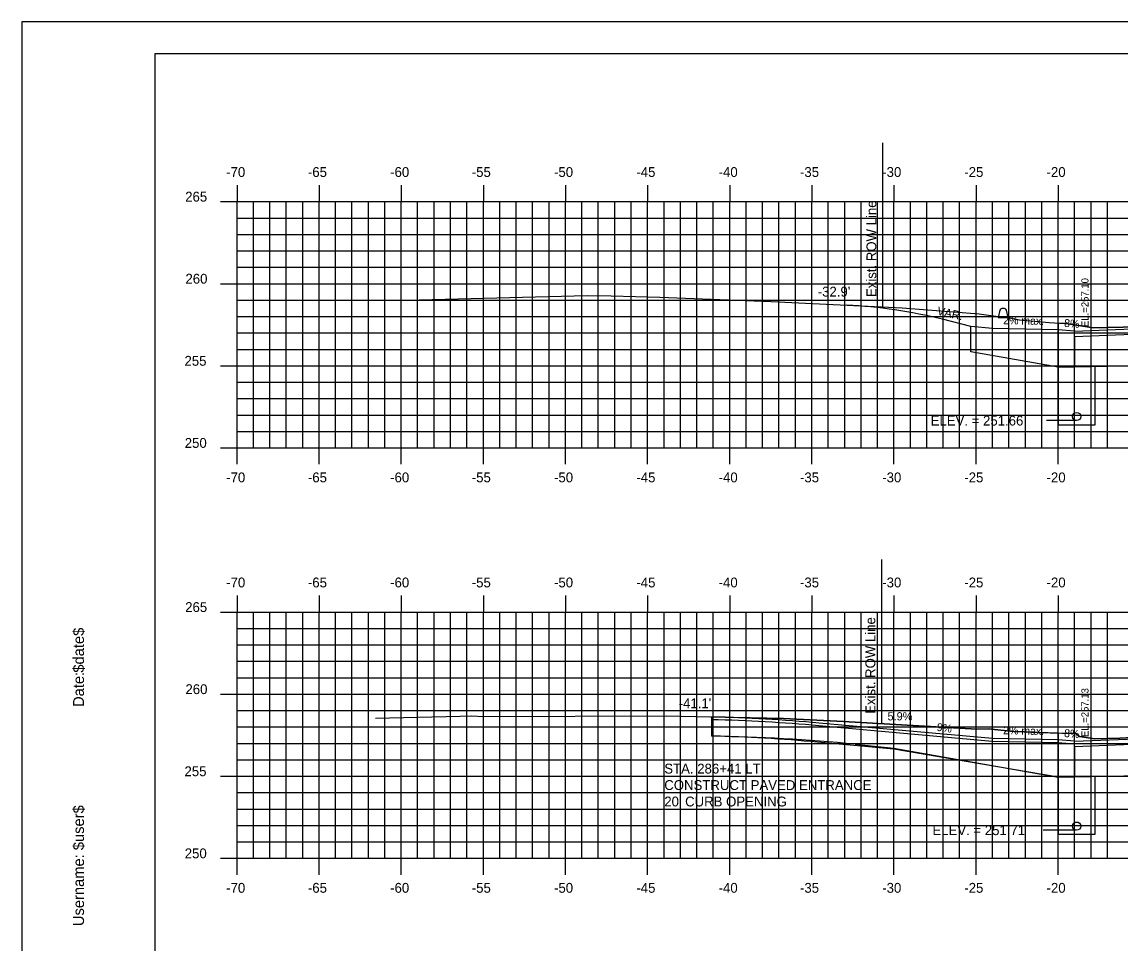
# Model space of a CAD drawing. Extents: x 856903 to 857073, y 366268 to 366378.
# Drawn here: x 856902.7 to 856969.5, y 366322.1 to 366378.2 of the extents above; entities that cross this region are included whole.
import ezdxf

# ---------------------------------------------------------------- set-up
doc = ezdxf.new("R2010")
doc.units = 0
for name, color, linetype in [('ANNOTATION', 7, 'Continuous'), ('BORDER', 7, 'Continuous'), ('D_Roadway_Drive_Gravel_LT', 7, 'Continuous'), ('D_Roadway_Drive_SubGrade', 7, 'Continuous'), ('D_Roadway_Edge_Shoulder', 7, 'Continuous'), ('D_Roadway_SubGrade', 7, 'Continuous'), ('D_Text_Standard', 7, 'Continuous'), ('E_ROW_Line', 7, 'Continuous'), ('H_V ANNOTATION', 7, 'Continuous'), ('JUNK COM EXC', 7, 'Continuous'), ('junk strct exc', 7, 'Continuous'), ('MAJOR', 7, 'Continuous'), ('MINOR', 7, 'Continuous'), ('PDRAIN', 7, 'Continuous'), ('PLOT BOUNDARY', 7, 'Continuous'), ('S_Curb_Type_3', 7, 'Continuous'), ('S_Roadway_Centerline', 7, 'Continuous'), ('TEXT', 7, 'Continuous')]:
    doc.layers.add(name, color=color, linetype=linetype)

msp = doc.modelspace()

# ---------------------------------------------------------------- linework, layer by layer
at = {"layer": 'BORDER'}
for p, q in [((857070.784, 366376.236), (856910.784, 366376.236)), ((856910.784, 366376.236), (856910.784, 366271.236))]:
    msp.add_line(p, q, dxfattribs=at)
at = {"layer": 'D_Roadway_Drive_Gravel_LT'}
for p, q in [((856960.471, 366359.632), (856958.739, 366360.065)), ((856960.471, 366358.094), (856960.471, 366359.632)), ((856961.784, 366359.501), (856960.471, 366359.632)), ((856965.784, 366359.421), (856961.784, 366359.501)), ((856966.784, 366359.341), (856965.784, 366359.421)), ((856966.784, 366359.007), (856966.784, 366359.341)), ((856961.784, 366334.523), (856951.234, 366335.473)), ((856961.769, 366334.357), (856951.219, 366335.307)), ((856955.784, 366333.892), (856951.129, 366334.311)), ((856965.781, 366334.277), (856961.781, 366334.357)), ((856965.784, 366334.443), (856961.784, 366334.523)), ((856961.784, 366334.523), (856961.784, 366334.523)), ((856966.784, 366334.196), (856965.771, 366334.277)), ((856966.784, 366334.363), (856965.784, 366334.443)), ((856966.784, 366334.03), (856966.784, 366334.363))]:
    msp.add_line(p, q, dxfattribs=at)
for centre, radius, start, end in [((856951.464, 366330.961), 30, 75.96376, 87.2318), ((856942.27, 366235.875), 100, 84.85724, 88.61888), ((856942.27, 366235.875), 99.833, 84.85724, 88.61657), ((856942.27, 366235.875), 98.833, 84.85724, 88.60257)]:
    msp.add_arc(centre, radius, start, end, dxfattribs=at)
at = {"layer": 'D_Roadway_Drive_SubGrade'}
for p, q in [((856965.784, 366357.147), (856960.471, 366358.094)), ((856966.784, 366357.167), (856965.784, 366357.147)), ((856944.68, 366335.846), (856944.68, 366334.679)), ((856965.784, 366332.17), (856955.784, 366333.892)), ((856966.784, 366332.19), (856965.784, 366332.17))]:
    msp.add_line(p, q, dxfattribs=at)
at = {"layer": 'D_Roadway_Edge_Shoulder'}
for points in [[(856966.784, 366359.341), (856974.784, 366359.661), (856985.784, 366359.881), (856996.784, 366359.661), (857004.785, 366359.341)], [(856966.784, 366334.363), (856974.784, 366334.683), (856985.784, 366334.903), (856996.784, 366334.683), (857004.785, 366334.363)]]:
    msp.add_lwpolyline(points, dxfattribs=at)
at = {"layer": 'D_Roadway_SubGrade'}
for points in [[(856974.784, 366359.327), (856966.784, 366359.007), (856966.784, 366357.167), (856974.784, 366357.327)], [(856974.784, 366334.35), (856966.784, 366334.03), (856966.784, 366332.19), (856974.784, 366332.35)]]:
    msp.add_lwpolyline(points, close=True, dxfattribs=at)
at = {"layer": 'D_Text_Standard'}
for points in [[(856966.909, 366353.896), (856965.746, 366353.896), (856965.066, 366353.896)], [(856966.909, 366328.946), (856965.544, 366328.946), (856964.864, 366328.946)]]:
    msp.add_lwpolyline(points, dxfattribs=at)
at = {"layer": 'E_ROW_Line'}
for p, q in [((856955.11, 366360.82), (856955.11, 366370.82)), ((856955.047, 366335.437), (856955.047, 366345.437))]:
    msp.add_line(p, q, dxfattribs=at)
at = {"layer": 'JUNK COM EXC'}
for points in [[(856970.642, 366359.617), (856967.936, 366359.549), (856966.278, 366359.805), (856966.269, 366359.812), (856966.267, 366359.811), (856966.192, 366359.813), (856965.784, 366359.836), (856965.784, 366357.147), (856974.784, 366357.327)], [(856965.784, 366334.855), (856964.556, 366334.889), (856963.708, 366334.937), (856963.082, 366334.961), (856961.517, 366335.116), (856960.827, 366335.095), (856952.722, 366335.574), (856949.051, 366335.741), (856946.005, 366335.814), (856944.68, 366335.846), (856944.68, 366334.679)], [(856953.429, 366334.186), (856955.784, 366333.951), (856965.784, 366332.17), (856965.784, 366334.855)], [(857005.784, 366334.674), (857004.443, 366334.819), (857002.913, 366334.984), (857002.611, 366334.676), (857002.347, 366334.388), (856998.4, 366334.53), (856996.854, 366334.558), (856988.735, 366334.939), (856985.845, 366335.02), (856977.64, 366334.888), (856975.733, 366334.868), (856969.543, 366334.552), (856968.014, 366334.513), (856967.076, 366334.658), (856966.809, 366334.862), (856966.744, 366334.828), (856965.784, 366334.855), (856965.784, 366332.17), (856974.784, 366332.35), (856985.784, 366332.57), (856996.784, 366332.35), (857005.784, 366332.17), (857005.784, 366334.674)]]:
    msp.add_lwpolyline(points, dxfattribs=at)
msp.add_arc((856942.508, 366218.264), 116.435, 84.61802, 88.93118, dxfattribs=at)
at = {"layer": 'junk strct exc'}
for points in [[(856965.784, 366357.147), (856965.784, 366353.646), (856968.034, 366353.646), (856968.034, 366357.192)], [(856965.784, 366332.197), (856965.784, 366328.696), (856968.034, 366328.696), (856968.034, 366332.215)]]:
    msp.add_lwpolyline(points, close=True, dxfattribs=at)
at = {"layer": 'MAJOR'}
for p, q in [((856915.784, 366368.238), (856915.784, 366367.236)), ((856920.784, 366368.238), (856920.784, 366367.236)), ((856925.784, 366368.238), (856925.784, 366367.236)), ((856930.784, 366368.238), (856930.784, 366367.236)), ((856935.784, 366368.238), (856935.784, 366367.236)), ((856940.784, 366368.238), (856940.784, 366367.236)), ((856945.784, 366368.238), (856945.784, 366367.236)), ((856950.784, 366368.238), (856950.784, 366367.236)), ((856955.784, 366368.238), (856955.784, 366367.236)), ((856960.784, 366368.238), (856960.784, 366367.236)), ((856965.784, 366368.238), (856965.784, 366367.236)), ((856914.782, 366367.236), (856915.784, 366367.236)), ((856915.784, 366367.236), (857055.784, 366367.236)), ((856915.784, 366352.236), (856915.784, 366367.236)), ((856915.784, 366352.236), (856915.784, 366367.236)), ((856915.784, 366367.236), (857055.784, 366367.236)), ((856920.784, 366352.236), (856920.784, 366367.236)), ((856925.784, 366352.236), (856925.784, 366367.236)), ((856930.784, 366352.236), (856930.784, 366367.236)), ((856935.784, 366352.236), (856935.784, 366367.236)), ((856940.784, 366352.236), (856940.784, 366367.236)), ((856945.784, 366352.236), (856945.784, 366367.236)), ((856950.784, 366352.236), (856950.784, 366367.236)), ((856955.784, 366352.236), (856955.784, 366367.236)), ((856960.784, 366352.236), (856960.784, 366367.236)), ((856965.784, 366352.236), (856965.784, 366367.236)), ((856914.782, 366362.236), (856915.784, 366362.236)), ((856915.784, 366362.236), (857055.784, 366362.236)), ((856914.782, 366357.236), (856915.784, 366357.236)), ((856915.784, 366357.236), (857055.784, 366357.236)), ((856914.782, 366352.236), (856915.784, 366352.236)), ((856915.784, 366352.236), (857055.784, 366352.236)), ((856915.784, 366352.236), (857055.784, 366352.236)), ((856915.784, 366351.234), (856915.784, 366352.236)), ((856920.784, 366351.234), (856920.784, 366352.236)), ((856925.784, 366351.234), (856925.784, 366352.236)), ((856930.784, 366351.234), (856930.784, 366352.236)), ((856935.784, 366351.234), (856935.784, 366352.236)), ((856940.784, 366351.234), (856940.784, 366352.236)), ((856945.784, 366351.234), (856945.784, 366352.236)), ((856950.784, 366351.234), (856950.784, 366352.236)), ((856955.784, 366351.234), (856955.784, 366352.236)), ((856960.784, 366351.234), (856960.784, 366352.236)), ((856965.784, 366351.234), (856965.784, 366352.236)), ((856915.784, 366343.238), (856915.784, 366342.236)), ((856920.784, 366343.238), (856920.784, 366342.236)), ((856925.784, 366343.238), (856925.784, 366342.236)), ((856930.784, 366343.238), (856930.784, 366342.236)), ((856935.784, 366343.238), (856935.784, 366342.236)), ((856940.784, 366343.238), (856940.784, 366342.236)), ((856945.784, 366343.238), (856945.784, 366342.236)), ((856950.784, 366343.238), (856950.784, 366342.236)), ((856955.784, 366343.238), (856955.784, 366342.236)), ((856960.784, 366343.238), (856960.784, 366342.236)), ((856965.784, 366343.238), (856965.784, 366342.236)), ((856914.782, 366342.236), (856915.784, 366342.236)), ((856915.784, 366342.236), (857055.784, 366342.236)), ((856915.784, 366327.236), (856915.784, 366342.236)), ((856915.784, 366327.236), (856915.784, 366342.236)), ((856915.784, 366342.236), (857055.784, 366342.236)), ((856920.784, 366327.236), (856920.784, 366342.236)), ((856925.784, 366327.236), (856925.784, 366342.236)), ((856930.784, 366327.236), (856930.784, 366342.236)), ((856935.784, 366327.236), (856935.784, 366342.236)), ((856940.784, 366327.236), (856940.784, 366342.236)), ((856945.784, 366327.236), (856945.784, 366342.236)), ((856950.784, 366327.236), (856950.784, 366342.236)), ((856955.784, 366327.236), (856955.784, 366342.236)), ((856960.784, 366327.236), (856960.784, 366342.236)), ((856965.784, 366327.236), (856965.784, 366342.236)), ((856914.782, 366337.236), (856915.784, 366337.236)), ((856915.784, 366337.236), (857055.784, 366337.236)), ((856914.782, 366332.236), (856915.784, 366332.236)), ((856915.784, 366332.236), (857055.784, 366332.236)), ((856914.782, 366327.236), (856915.784, 366327.236)), ((856915.784, 366327.236), (857055.784, 366327.236)), ((856915.784, 366327.236), (857055.784, 366327.236)), ((856915.784, 366326.234), (856915.784, 366327.236)), ((856920.784, 366326.234), (856920.784, 366327.236)), ((856925.784, 366326.234), (856925.784, 366327.236)), ((856930.784, 366326.234), (856930.784, 366327.236)), ((856935.784, 366326.234), (856935.784, 366327.236)), ((856940.784, 366326.234), (856940.784, 366327.236)), ((856945.784, 366326.234), (856945.784, 366327.236)), ((856950.784, 366326.234), (856950.784, 366327.236)), ((856955.784, 366326.234), (856955.784, 366327.236)), ((856960.784, 366326.234), (856960.784, 366327.236)), ((856965.784, 366326.234), (856965.784, 366327.236))]:
    msp.add_line(p, q, dxfattribs=at)
at = {"layer": 'MINOR'}
for p, q in [((856916.784, 366352.236), (856916.784, 366367.236)), ((856917.784, 366352.236), (856917.784, 366367.236)), ((856918.784, 366352.236), (856918.784, 366367.236)), ((856919.784, 366352.236), (856919.784, 366367.236)), ((856921.784, 366352.236), (856921.784, 366367.236)), ((856922.784, 366352.236), (856922.784, 366367.236)), ((856923.784, 366352.236), (856923.784, 366367.236)), ((856924.784, 366352.236), (856924.784, 366367.236)), ((856926.784, 366352.236), (856926.784, 366367.236)), ((856927.784, 366352.236), (856927.784, 366367.236)), ((856928.784, 366352.236), (856928.784, 366367.236)), ((856929.784, 366352.236), (856929.784, 366367.236)), ((856931.784, 366352.236), (856931.784, 366367.236)), ((856932.784, 366352.236), (856932.784, 366367.236)), ((856933.784, 366352.236), (856933.784, 366367.236)), ((856934.784, 366352.236), (856934.784, 366367.236)), ((856936.784, 366352.236), (856936.784, 366367.236)), ((856937.784, 366352.236), (856937.784, 366367.236)), ((856938.784, 366352.236), (856938.784, 366367.236)), ((856939.784, 366352.236), (856939.784, 366367.236)), ((856941.784, 366352.236), (856941.784, 366367.236)), ((856942.784, 366352.236), (856942.784, 366367.236)), ((856943.784, 366352.236), (856943.784, 366367.236)), ((856944.784, 366352.236), (856944.784, 366367.236)), ((856946.784, 366352.236), (856946.784, 366367.236)), ((856947.784, 366352.236), (856947.784, 366367.236)), ((856948.784, 366352.236), (856948.784, 366367.236)), ((856949.784, 366352.236), (856949.784, 366367.236)), ((856951.784, 366352.236), (856951.784, 366367.236)), ((856952.784, 366352.236), (856952.784, 366367.236)), ((856953.784, 366352.236), (856953.784, 366367.236)), ((856954.784, 366352.236), (856954.784, 366367.236)), ((856956.784, 366352.236), (856956.784, 366367.236)), ((856957.784, 366352.236), (856957.784, 366367.236)), ((856958.784, 366352.236), (856958.784, 366367.236)), ((856959.784, 366352.236), (856959.784, 366367.236)), ((856961.784, 366352.236), (856961.784, 366367.236)), ((856962.784, 366352.236), (856962.784, 366367.236)), ((856963.784, 366352.236), (856963.784, 366367.236)), ((856964.784, 366352.236), (856964.784, 366367.236)), ((856966.784, 366352.236), (856966.784, 366367.236)), ((856967.784, 366352.236), (856967.784, 366367.236)), ((856968.784, 366352.236), (856968.784, 366367.236)), ((856915.784, 366366.236), (857055.784, 366366.236)), ((856915.784, 366366.236), (856916.786, 366366.236)), ((856915.784, 366365.236), (857055.784, 366365.236)), ((856915.784, 366365.236), (856916.786, 366365.236)), ((856915.784, 366364.236), (857055.784, 366364.236)), ((856915.784, 366364.236), (856916.786, 366364.236)), ((856915.784, 366363.236), (857055.784, 366363.236)), ((856915.784, 366363.236), (856916.786, 366363.236)), ((856915.784, 366361.236), (857055.784, 366361.236)), ((856915.784, 366361.236), (856916.786, 366361.236)), ((856915.784, 366360.236), (857055.784, 366360.236)), ((856915.784, 366360.236), (856916.786, 366360.236)), ((856915.784, 366359.236), (857055.784, 366359.236)), ((856915.784, 366359.236), (856916.786, 366359.236)), ((856915.784, 366358.236), (857055.784, 366358.236)), ((856915.784, 366358.236), (856916.786, 366358.236)), ((856915.784, 366356.236), (857055.784, 366356.236)), ((856915.784, 366356.236), (856916.786, 366356.236)), ((856915.784, 366355.236), (857055.784, 366355.236)), ((856915.784, 366355.236), (856916.786, 366355.236)), ((856915.784, 366354.236), (857055.784, 366354.236)), ((856915.784, 366354.236), (856916.786, 366354.236)), ((856915.784, 366353.236), (857055.784, 366353.236)), ((856915.784, 366353.236), (856916.786, 366353.236)), ((856916.784, 366327.236), (856916.784, 366342.236)), ((856917.784, 366327.236), (856917.784, 366342.236)), ((856918.784, 366327.236), (856918.784, 366342.236)), ((856919.784, 366327.236), (856919.784, 366342.236)), ((856921.784, 366327.236), (856921.784, 366342.236)), ((856922.784, 366327.236), (856922.784, 366342.236)), ((856923.784, 366327.236), (856923.784, 366342.236)), ((856924.784, 366327.236), (856924.784, 366342.236)), ((856926.784, 366327.236), (856926.784, 366342.236)), ((856927.784, 366327.236), (856927.784, 366342.236)), ((856928.784, 366327.236), (856928.784, 366342.236)), ((856929.784, 366327.236), (856929.784, 366342.236)), ((856931.784, 366327.236), (856931.784, 366342.236)), ((856932.784, 366327.236), (856932.784, 366342.236)), ((856933.784, 366327.236), (856933.784, 366342.236)), ((856934.784, 366327.236), (856934.784, 366342.236)), ((856936.784, 366327.236), (856936.784, 366342.236)), ((856937.784, 366327.236), (856937.784, 366342.236)), ((856938.784, 366327.236), (856938.784, 366342.236)), ((856939.784, 366327.236), (856939.784, 366342.236)), ((856941.784, 366327.236), (856941.784, 366342.236)), ((856942.784, 366327.236), (856942.784, 366342.236)), ((856943.784, 366327.236), (856943.784, 366342.236)), ((856944.784, 366327.236), (856944.784, 366342.236)), ((856946.784, 366327.236), (856946.784, 366342.236)), ((856947.784, 366327.236), (856947.784, 366342.236)), ((856948.784, 366327.236), (856948.784, 366342.236)), ((856949.784, 366327.236), (856949.784, 366342.236)), ((856951.784, 366327.236), (856951.784, 366342.236)), ((856952.784, 366327.236), (856952.784, 366342.236)), ((856953.784, 366327.236), (856953.784, 366342.236)), ((856954.784, 366327.236), (856954.784, 366342.236)), ((856956.784, 366327.236), (856956.784, 366342.236)), ((856957.784, 366327.236), (856957.784, 366342.236)), ((856958.784, 366327.236), (856958.784, 366342.236)), ((856959.784, 366327.236), (856959.784, 366342.236)), ((856961.784, 366327.236), (856961.784, 366342.236)), ((856962.784, 366327.236), (856962.784, 366342.236)), ((856963.784, 366327.236), (856963.784, 366342.236)), ((856964.784, 366327.236), (856964.784, 366342.236)), ((856966.784, 366327.236), (856966.784, 366342.236)), ((856967.784, 366327.236), (856967.784, 366342.236)), ((856968.784, 366327.236), (856968.784, 366342.236)), ((856915.784, 366341.236), (857055.784, 366341.236)), ((856915.784, 366341.236), (856916.786, 366341.236)), ((856915.784, 366340.236), (857055.784, 366340.236)), ((856915.784, 366340.236), (856916.786, 366340.236)), ((856915.784, 366339.236), (857055.784, 366339.236)), ((856915.784, 366339.236), (856916.786, 366339.236)), ((856915.784, 366338.236), (857055.784, 366338.236)), ((856915.784, 366338.236), (856916.786, 366338.236)), ((856915.784, 366336.236), (857055.784, 366336.236)), ((856915.784, 366336.236), (856916.786, 366336.236)), ((856915.784, 366335.236), (857055.784, 366335.236)), ((856915.784, 366335.236), (856916.786, 366335.236)), ((856915.784, 366334.236), (857055.784, 366334.236)), ((856915.784, 366334.236), (856916.786, 366334.236)), ((856915.784, 366333.236), (857055.784, 366333.236)), ((856915.784, 366333.236), (856916.786, 366333.236)), ((856915.784, 366331.236), (857055.784, 366331.236)), ((856915.784, 366331.236), (856916.786, 366331.236)), ((856915.784, 366330.236), (857055.784, 366330.236)), ((856915.784, 366330.236), (856916.786, 366330.236)), ((856915.784, 366329.236), (857055.784, 366329.236)), ((856915.784, 366329.236), (856916.786, 366329.236)), ((856915.784, 366328.236), (857055.784, 366328.236)), ((856915.784, 366328.236), (856916.786, 366328.236))]:
    msp.add_line(p, q, dxfattribs=at)
at = {"layer": 'PDRAIN'}
for points in [[(856965.784, 366357.147), (856965.784, 366353.646), (856968.034, 366353.646), (856968.034, 366357.192)], [(856965.784, 366332.17), (856965.784, 366328.696), (856968.034, 366328.696), (856968.034, 366332.215)]]:
    msp.add_lwpolyline(points, dxfattribs=at)
for centre in [(856966.909, 366354.146), (856966.909, 366329.196)]:
    msp.add_circle(centre, 0.25, dxfattribs=at)
at = {"layer": 'PLOT BOUNDARY'}
msp.add_lwpolyline([(856902.691, 366268.177), (857072.691, 366268.177), (857072.691, 366378.177), (856902.691, 366378.177)], close=True, dxfattribs=at)
at = {"layer": 'S_Curb_Type_3'}
for points in [[(856962.224, 366360.621), (856962.122, 366360.176), (856962.747, 366360.176), (856962.644, 366360.621)], [(856962.522, 366360.717), (856962.346, 366360.717)]]:
    msp.add_lwpolyline(points, dxfattribs=at)
for centre, start, end in [((856962.346, 366360.592), 90, 167.00538), ((856962.522, 366360.592), 12.99462, 90)]:
    msp.add_arc(centre, 0.125, start, end, dxfattribs=at)
at = {"layer": 'S_Roadway_Centerline'}
for points in [[(856926.102, 366361.23), (856937.114, 366361.519), (856938.557, 366361.495), (856941.536, 366361.421), (856948.307, 366361.148), (856956.275, 366360.763), (856960.974, 366360.396), (856962.556, 366360.18), (856962.747, 366360.176), (856963.243, 366360.069), (856963.429, 366360.037), (856965.244, 366359.866), (856966.192, 366359.813), (856966.267, 366359.811), (856966.269, 366359.812), (856966.278, 366359.805), (856967.936, 366359.549), (856970.642, 366359.617)], [(856924.214, 366335.769), (856929.369, 366335.883), (856930.079, 366335.905), (856930.79, 366335.877), (856941.943, 366335.912), (856949.051, 366335.741), (856952.722, 366335.574), (856960.827, 366335.095), (856961.517, 366335.116), (856963.082, 366334.961), (856963.708, 366334.937), (856964.556, 366334.889), (856966.744, 366334.828), (856966.809, 366334.862), (856967.076, 366334.658), (856968.014, 366334.513), (856969.543, 366334.552), (856975.733, 366334.868)]]:
    msp.add_lwpolyline(points, dxfattribs=at)

# ---------------------------------------------------------------- texts
at = {"layer": 'ANNOTATION'}
for s, p in [('STA. 286+41 LT.', (856941.8, 366332.398)), ('CONSTRUCT PAVED ENTRANCE', (856941.8, 366331.396)), ("20' CURB OPENING", (856941.8, 366330.394))]:
    msp.add_text(s, height=0.6, dxfattribs=at).set_placement(p)
at = {"layer": 'BORDER'}
for s, p in [('$date$', (856906.469, 366338.542)), ('Date:', (856906.469, 366336.453)), ('$user$', (856906.469, 366327.728)), ('Username:', (856906.469, 366323.104))]:
    msp.add_text(s, height=0.6696, rotation=90, dxfattribs=at).set_placement(p)
at = {"layer": 'D_Roadway_Drive_Gravel_LT'}
for s, rotation, p in [('2% max.', 358.80778, (856962.43, 366359.771)), ('8%', 355.42608, (856966.13, 366359.608)), ('9%', 352.59308, (856958.368, 366335.003)), ('2% max.', 358.80778, (856962.43, 366334.793)), ('8%', 355.42608, (856966.13, 366334.63))]:
    msp.add_text(s, height=0.48, rotation=rotation, dxfattribs=at).set_placement(p)
at = {"layer": 'D_Text_Standard'}
for s, height, rotation, p in [(' EL.=257.10', 0.4335, 90, (856967.63, 366359.435)), ('VAR.', 0.51, 347.36887, (856958.374, 366360.35)), (' EL.=257.13', 0.4335, 90, (856967.63, 366334.457))]:
    msp.add_text(s, height=height, rotation=rotation, dxfattribs=at).set_placement(p)
for s, p in [("-32.9'", (856951.144, 366361.451)), ('ELEV. = 251.66', (856958.019, 366353.596)), ("-41.1'", (856942.678, 366336.376)), ('ELEV. = 251.71', (856958.127, 366328.646))]:
    msp.add_text(s, height=0.6, dxfattribs=at).set_placement(p)
at = {"layer": 'E_ROW_Line'}
for p in [(856954.71, 366361.42), (856954.647, 366336.037)]:
    msp.add_text('Exist. ROW Line', height=0.6, rotation=90, dxfattribs=at).set_placement(p)
at = {"layer": 'H_V ANNOTATION'}
for s, p in [('-70', (856915.126, 366368.736)), ('-65', (856920.102, 366368.736)), ('-60', (856925.11, 366368.736)), ('-55', (856930.08, 366368.736)), ('-50', (856935.088, 366368.736)), ('-45', (856940.102, 366368.736)), ('-40', (856945.11, 366368.736)), ('-35', (856950.064, 366368.736)), ('-30', (856955.072, 366368.736)), ('-25', (856960.069, 366368.736)), ('-20', (856965.077, 366368.736)), ('265', (856912.63, 366367.236)), ('260', (856912.646, 366362.236)), ('255', (856912.587, 366357.236)), ('250', (856912.603, 366352.236)), ('-70', (856915.126, 366350.136)), ('-65', (856920.102, 366350.136)), ('-60', (856925.11, 366350.136)), ('-55', (856930.08, 366350.136)), ('-50', (856935.088, 366350.136)), ('-45', (856940.102, 366350.136)), ('-40', (856945.11, 366350.136)), ('-35', (856950.064, 366350.136)), ('-30', (856955.072, 366350.136)), ('-25', (856960.069, 366350.136)), ('-20', (856965.077, 366350.136)), ('-70', (856915.126, 366343.736)), ('-65', (856920.102, 366343.736)), ('-60', (856925.11, 366343.736)), ('-55', (856930.08, 366343.736)), ('-50', (856935.088, 366343.736)), ('-45', (856940.102, 366343.736)), ('-40', (856945.11, 366343.736)), ('-35', (856950.064, 366343.736)), ('-30', (856955.072, 366343.736)), ('-25', (856960.069, 366343.736)), ('-20', (856965.077, 366343.736)), ('265', (856912.63, 366342.236)), ('260', (856912.646, 366337.236)), ('255', (856912.587, 366332.236)), ('250', (856912.603, 366327.236)), ('-70', (856915.126, 366325.136)), ('-65', (856920.102, 366325.136)), ('-60', (856925.11, 366325.136)), ('-55', (856930.08, 366325.136)), ('-50', (856935.088, 366325.136)), ('-45', (856940.102, 366325.136)), ('-40', (856945.11, 366325.136)), ('-35', (856950.064, 366325.136)), ('-30', (856955.072, 366325.136)), ('-25', (856960.069, 366325.136)), ('-20', (856965.077, 366325.136))]:
    msp.add_text(s, height=0.6, dxfattribs=at).set_placement(p)
at = {"layer": 'MAJOR'}
for p in [(856915.78, 366352.236), (856915.78, 366327.236)]:
    msp.add_text('-', height=0.00000006, rotation=53.1301, dxfattribs=at).set_placement(p)
at = {"layer": 'TEXT'}
msp.add_text('5.9%', height=0.5, dxfattribs=at).set_placement((856955.389, 366335.635))

doc.saveas('drawing.dxf')
